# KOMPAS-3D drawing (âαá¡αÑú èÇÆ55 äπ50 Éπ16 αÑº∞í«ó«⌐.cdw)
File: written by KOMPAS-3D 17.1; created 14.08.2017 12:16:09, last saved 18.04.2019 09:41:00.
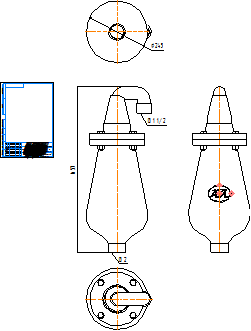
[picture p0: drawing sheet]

Sheet 1: A4, portrait

Title block, sheet 1: name: Гранрег КАТ55 Ду50 Ру16 резьбовой; material: Внимание! Данный продукт является объектом авторского права ООО «Торговый Дом АДЛ». / Запрещается изменение, копирование, распространение / (в том числе путем копирования на другие сайты и ресурсы в Интернете) / или любое иное использование информации и объектов без предварительного / согласия правообладателя (ООО «Торговый Дом АДЛ»).; mass: 116,3; sheets: 1; organisation: ООО "Торговый дом АДЛ"; sheet format: A4; stored path: \\adlc.lan\data\АДЛ_ПКД\3D-модели\ADL production\Клапаны КАТ ГРАНРЕГ\КАТ55\KOMPAS 2D\Гранрег КАТ55 Ду50 Ру16 резьбовой.cdw

Views: Вид 1, Проекционный вид 2, Проекционный вид 3, Проекционный вид 4
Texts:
  kka
  adl
Dimensions and other numbers on the sheet: 657; 245; 1:1; 1; 116,3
